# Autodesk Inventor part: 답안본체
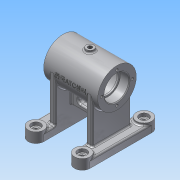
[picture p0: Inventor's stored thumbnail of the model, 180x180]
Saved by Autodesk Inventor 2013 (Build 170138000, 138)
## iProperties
Created: 2015-11
Part Number: 답안본체
Material: 알루미늄 6061
Document SubType Name: Modeling
Designer: ST3
Density: 2.71 g/cm^3
Mass: 357.973 g
Surface Area: 459.687 cm^2
Volume: 132.093 cm^3
Author: ST3
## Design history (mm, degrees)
sketch "스케치1"
  geometry: L1 (-35, 0)-(35, 0); L2 (-35, 16)-(-35, 25); L3 (-35, 25)-(35, 25); L4 (35, 25)-(35, 16); L5 (35, 16)-(23, 16); L6 (23, 16)-(23, 14); L7 (23, 14)-(21, 14); L8 (21, 14)-(21, 21); L9 (21, 21)-(-21, 21); L10 (-21, 21)-(-21, 14); L11 (-21, 14)-(-23, 14); L12 (-23, 14)-(-23, 16); L13 (-23, 16)-(-35, 16); 1 further point
  constraints: 26 end point, 10 parallel, 2 perpendicular, 1 horizontal
  dimensions: "d0" = 0 distance from line of point (0, 0) L1; "d1" = 70 distance of L1.start L1.end; "d2" = 35 distance of point (0, 0) L1.start (= 0.5 x d1); "d3" = 70 distance between parallel lines of L4 L2; "d4" = 42 diameter of L9 L1; "d5" = 50 diameter of L3 L1; "d6" = 28 diameter of L7 L1; "d7" = 28 diameter of L11 L1; "d8" = 32 diameter of L13 L1; "d9" = 32 diameter of L5 L1; "d10" = 12 distance of L4.end L5.end; "d11" = 12 distance of L12.end L2.start; "d12" = 42 distance between parallel lines of L8 L10; "d13" = 2 distance of L10.end L11.end; "d14" = 0 distance from line of L2 L1.start
revolve "회전1" sketch "스케치1" stored, may be unused: angle "d15" = 90 deg
node "작업 평면1"
sketch "스케치3"
  geometry: L1 (40, 40)-(40, -40); L2 (20, 40)-(20, -40); A1 r 10 centre (30, 40) between (40, 40) and (20, 40); A2 r 10 centre (30, -40) between (20, -40) and (40, -40); 1 further point
  constraints: 4 end point, 4 point on circle, 3 tangent, 2 centre point, 1 vertical
  dimensions: "d28" = 80 distance of A2.centre A1.centre; "d32" = 20 diameter of A1; "d33" = 20 diameter of A2; "d34" = 40 vertical distance of point (0, 0) A1.centre (= 0.5 x d28); "d44" = 40 distance from line of L1 point (0, 0); "d45" = 20 distance from line of L2 point (0, 0)
extrude "돌출2" join sketch "스케치3" distance "d35" = 10; taper "d36" = 0 deg
sketch "스케치4"
  geometry: L1 (10, 0)-(10, -80) reference; L2 (2, -15)-(10, -15); L3 (10, -15)-(10, -65); L4 (10, -65)-(2, -65); L5 (2, -65)-(2, -15); 1 further point
  constraints: 8 end point, 2 parallel, 1 horizontal, 1 perpendicular, 1 point on line
  dimensions: "d37" = 8 distance between parallel lines of L3 L5; "d39" = 50 distance between parallel lines of L4 L2; "d40" = 25 distance from line of point (30, -40) L2 (= 0.5 x d39)
extrude "돌출3" join sketch "스케치4" stored distance "d41" = 10; taper "d42" = 0 deg
sketch "스케치5"
  geometry: L1 (35, -25)-(-35, -25) reference; L2 (20, -45)-(-20, -45); L3 (-20, -58)-(-20, 0) reference; L4 (20, -58)-(20, 0) reference; 1 further point
  constraints: 2 end point
feature "리브1" sketch "스케치5" dims "d48" = 1, "d49" = 8, "d50" = 0, "d51" = 0, "d52" = 1, "d53" = 1
sketch "스케치6"
  geometry: L1 (40, 0)-(0, 0) reference; L2 (0, 43.322)-(-20, 43.322) reference; L3 (40, 43.322)-(60, 43.322) reference; L4 (28, 6.822)-(12, 6.822); L5 (28, 13.822)-(12, 13.822); A1 r 3.5 centre (28, 10.322) between (28, 6.822) and (28, 13.822); A2 r 3.5 centre (12, 10.322) between (12, 13.822) and (12, 6.822); 2 further points
  constraints: 4 end point, 4 point on circle, 3 tangent, 2 centre point, 1 midpoint, 1 parallel
  dimensions: "d57" = 7 diameter of A1; "d58" = 7 diameter of A2; "d59" = 33 distance from line of A2.centre L2; "d60" = 33 distance from line of A1.centre L3; "d161" = 8 horizontal distance of A2.centre point (20, -24.678); "d162" = 8 horizontal distance of A1.centre point (20, -24.678)
extrude "돌출4" cut sketch "스케치6" stored distance "d61" = 10; taper "d62" = 0 deg
fillet "모깎기1" dims "d63" = 2
fillet "모깎기2" dims "d64" = 2
fillet "모깎기3" dims "d65" = 2
fillet "모깎기4" dims "d66" = 2
chamfer "모따기1" distance "d67" = 1; stored, may be unused: second distance "d68" = 2, angle "d69" = 45 deg
fillet "모깎기5" dims "d70" = 3
fillet "모깎기6" dims "d71" = 0.3
sketch "스케치7" dims "d72" = 40
  geometry: C1 r 25 at (0, 0) reference; C2 r 17 at (0, 0) reference; 2 further points
  constraints: 1 coincident, 1 horizontal alignment, 2 other
  dimensions: "d74" = 0 vertical distance of point (-20, 0) C1.centre
hole "구멍1" sketch "스케치7" at (-20, 0) diameter "d75" = 3.242; stored, may be unused: countersink angle "d79" = 90 deg, drill point angle "d81" = 118 deg; dims "d76" = 8, "d77" = 4, "d78" = 2, "d80" = 10
node "작업 평면3"
sketch "스케치8"
  geometry: C1 r 5 at (0, 0); 1 further point
  constraints: 1 centre point, 1 coincident
  dimensions: "d86" = 10 diameter of C1
extrude "돌출5" join sketch "스케치8" stored distance "d88" = 10; taper "d89" = 0 deg
sketch "스케치9"
  geometry: C1 r 5 at (0, 0) reference
hole "구멍2" sketch "스케치9" at (0, 0) diameter "d93" = 5.188; stored, may be unused: countersink angle "d97" = 90 deg, drill point angle "d99" = 118 deg; dims "d94" = 8, "d95" = 4, "d96" = 2, "d98" = 10
sketch "스케치10"
  geometry: L1 (70, -80)-(70, 0) reference; L2 (50, 0)-(50, -80) reference; C1 r 10 at (0, 0); C2 r 10 at (0, -80); A1 r 10 centre (0, 0) between (10, 0) and (-10, 0) reference; A2 r 10 centre (0, -80) between (-10, -80) and (10, -80) reference; A3 r 10 centre (60, 0) between (70, 0) and (50, 0) reference; A4 r 10 centre (60, -80) between (50, -80) and (70, -80) reference; 3 further points
  constraints: 4 coincident, 2 centre point, 2 concentric, 2 horizontal alignment, 4 other
extrude "돌출6" join sketch "스케치10" distance "d103" = 3; taper "d104" = 0 deg
sketch "스케치11"
  geometry: L1 (70, 0)-(70, 80) reference; L2 (50, 80)-(50, 0) reference; L3 (10, 80)-(10, 0) reference; L4 (-10, 0)-(-10, 80) reference; C1 r 10 at (0, 0) reference; A1 r 10 centre (60, 80) between (70, 80) and (50, 80) reference; A2 r 10 centre (60, 0) between (50, 0) and (70, 0) reference; A3 r 10 centre (0, 80) between (10, 80) and (-10, 80) reference; A4 r 10 centre (0, 0) between (-10, 0) and (10, 0) reference; 1 further point
hole "구멍3" sketch "스케치11" at (0, 0), (60, 0), (60, 80), (0, 80) diameter "d105" = 6; stored, may be unused: countersink angle "d109" = 82 deg, drill point angle "d111" = 0 deg; dims "d106" = 8, "d107" = 12, "d108" = 4, "d110" = 13
fillet "모깎기7" dims "d112" = 2
fillet "모깎기8" dims "d113" = 2
fillet "모깎기9" dims "d114" = 2
node "작업 평면4"
sketch "스케치15"
  geometry: L1 (-25.873, 3.002)-(25.873, 3.002); L2 (25.873, 3.002)-(25.873, -3.002); L3 (25.873, -3.002)-(-25.873, -3.002); L4 (-25.873, -3.002)-(-25.873, 3.002); L5 (-25.873, 0)-(25.873, 0); L6 (0, -3.002)-(0, 3.002); L7 (-35, 25)-(35, 25) reference; L8 (-35, -25)-(-35, 25) reference; 1 further point
  constraints: 4 end point, 4 midpoint, 2 other
  dimensions: "d127" = 25 distance between parallel lines of L7 L5; "d128" = 35 distance between parallel lines of L8 L6
feature "엠보싱1" sketch "스케치15" dims "d129" = 0.5, "d130" = 0
sketch "스케치16"
  geometry: L1 (0, 0)-(26.734, -46.305); L2 (2.536, -45)-(-2.536, -45) reference; L3 (0, 0)-(0, -45); L4 (12.5, -21.651)-(30.959, -10.993); C1 r 1.621 at (20, 0) reference; C2 r 1.621 at (0, -20) reference; C3 r 1.621 at (-20, 0) reference; C4 r 1.621 at (0, 20) reference; C5 r 17 at (0, 0) reference; 4 further points
  constraints: 6 end point, 1 midpoint, 1 point on line, 3 other
  dimensions: "d141" = 30 deg angle of L3 L1; "d142" = 90 deg angle of L1 L4
  node "투영된 루프4"
node "작업 평면7"
node "작업 평면10"
  node "작업 평면9"
sketch "스케치17"
  geometry: C1 r 6 at (0, 0); 1 further point
  constraints: 1 centre point, 1 coincident
  dimensions: "d144" = 12 diameter of C1
extrude "돌출7" join sketch "스케치17" stored distance "d146" = 3; taper "d147" = 0 deg
sketch "스케치18"
  geometry: C1 r 6 at (0, 0) reference
hole "구멍5" sketch "스케치18" at (0, 0) diameter "d148" = 5.188; stored, may be unused: countersink angle "d152" = 82 deg, drill point angle "d154" = 0 deg; dims "d149" = 8, "d150" = 12, "d151" = 4, "d153" = 13
fillet "모깎기11" dims "d155" = 2
fillet "모깎기12" dims "d156" = 0.3
chamfer "모따기2" distance "d157" = 1; stored, may be unused: second distance "d158" = 2, angle "d159" = 45 deg
node "솔리드1"
mirror "대칭2"
mirror "대칭3"
pattern_circular "원형 패턴1" dims angle "d83" = 360 deg
mirror "대칭4"
node "투영된 루프1"
node "투영된 루프2"
node "투영된 루프3"
other parameters: "d16" = -68, "d85" = 28, "d126" = -44.5, "d143" = 3
